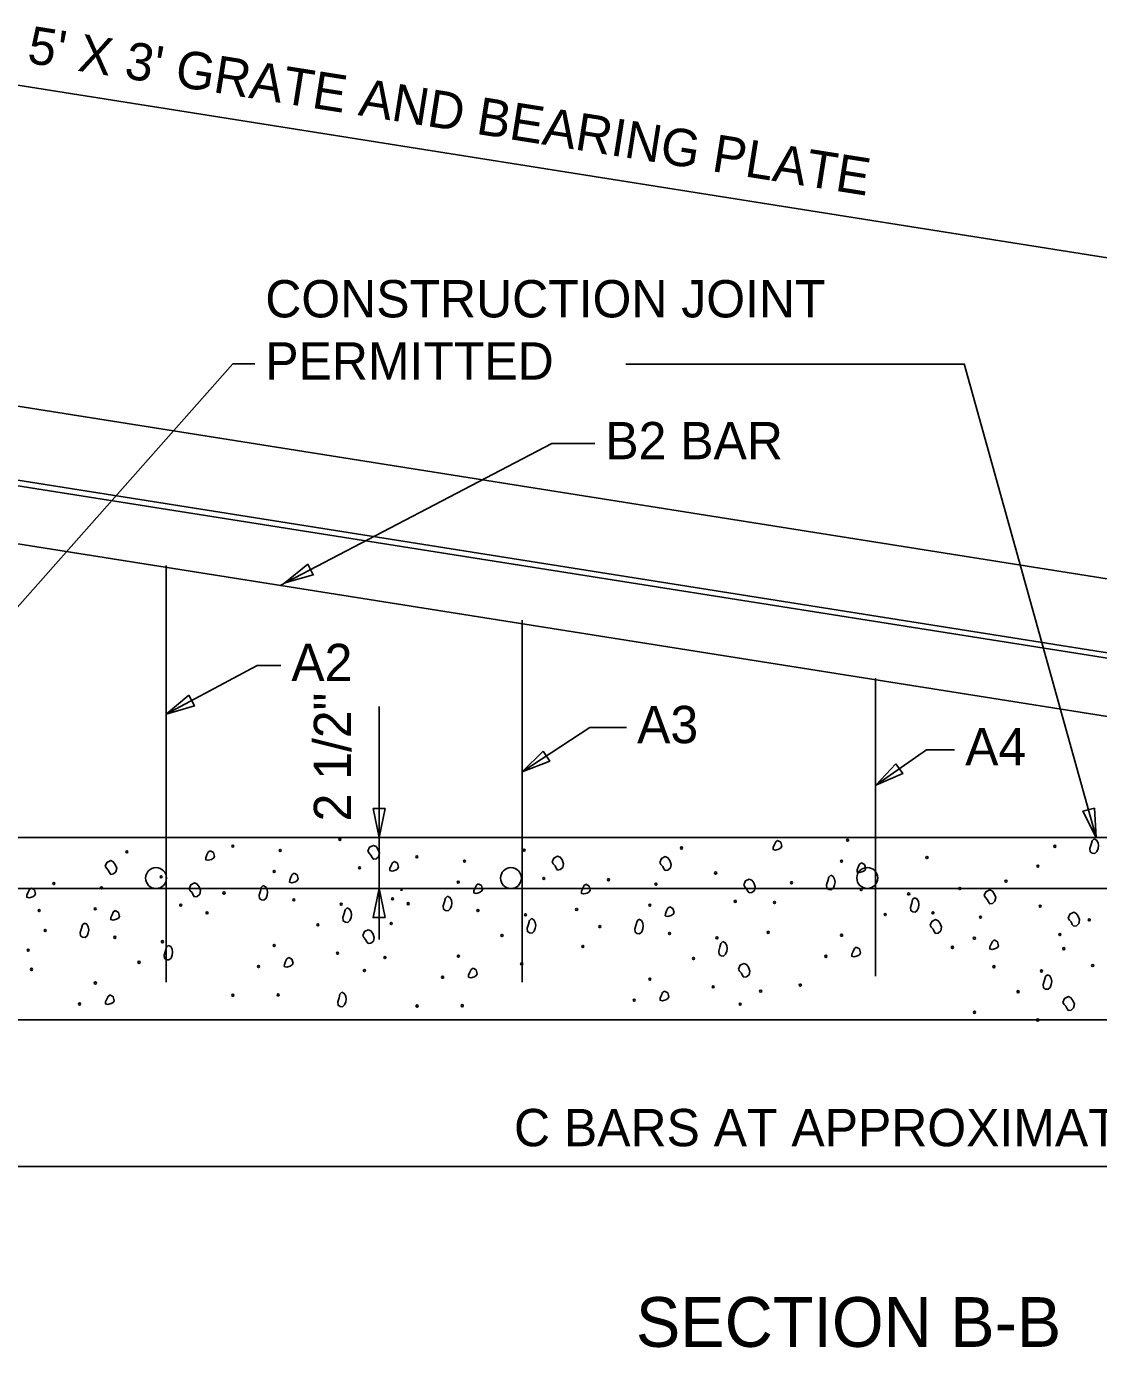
# Model space of a CAD drawing. Extents: x -439.2 to -407.9, y -458.1 to -436.2.
# Drawn here: x -435.83 to -431.52, y -451.85 to -446.54 of the extents above; entities that cross this region are included whole.
import ezdxf

# ---------------------------------------------------------------- set-up
doc = ezdxf.new("R2010")
doc.units = 0
doc.layers.add('Level 4', color=7, linetype='Continuous')
doc.layers.add('Level 45', color=7, linetype='Continuous')

msp = doc.modelspace()

# ---------------------------------------------------------------- linework, layer by layer
at = {"layer": 'Level 4'}
for p, q in [((-436.1395, -446.7284), (-430.9827, -447.5452)), ((-439.1627, -447.54), (-425.6904, -449.6734)), ((-436.6846, -449.7952), (-434.9984, -447.8922)), ((-434.9984, -447.8922), (-434.9111, -447.8922)), ((-433.4201, -447.8926), (-432.0607, -447.8926)), ((-431.5296, -449.7955), (-432.0609, -447.8922)), ((-434.8086, -448.7823), (-433.7176, -448.2124)), ((-433.7176, -448.2124), (-433.5449, -448.2124)), ((-436.4245, -448.2926), (-431.261, -449.11)), ((-436.4193, -448.2716), (-431.2564, -449.0896)), ((-436.5705, -448.5037), (-430.4973, -449.4655)), ((-435.2674, -448.7021), (-435.2674, -450.3769)), ((-433.8363, -448.9226), (-433.8363, -450.3769)), ((-435.2674, -449.3001), (-434.9012, -449.104)), ((-434.9012, -449.104), (-434.8066, -449.104)), ((-432.4167, -449.1557), (-432.4167, -450.3527)), ((-434.4116, -450.2055), (-434.4116, -449.2691)), ((-433.8363, -449.5318), (-433.5653, -449.3534)), ((-433.5653, -449.3534), (-433.4172, -449.3534)), ((-432.4162, -449.585), (-432.2115, -449.4425)), ((-432.2115, -449.4425), (-432.0991, -449.4425)), ((-436.4193, -449.7952), (-425.6904, -449.7952)), ((-436.9348, -450.001), (-431.0317, -450.001)), ((-434.3258, -450.0072), (-434.3171, -450.0072)), ((-437.1984, -450.5281), (-425.6904, -450.5281)), ((-425.6902, -451.1174), (-437.1989, -451.1174))]:
    msp.add_line(p, q, dxfattribs=at)
for points in [[(-434.6982, -448.6974), (-434.79, -448.7725), (-434.6759, -448.7401)], [(-435.1764, -449.224), (-435.2674, -449.3001), (-435.1536, -449.2665)], [(-433.7525, -449.4478), (-433.8363, -449.5318), (-433.726, -449.4881)], [(-432.3347, -449.4988), (-432.4162, -449.585), (-432.3071, -449.5384)], [(-434.4357, -449.679), (-434.4116, -449.7952), (-434.3875, -449.679)], [(-431.5376, -449.6771), (-431.5296, -449.7955), (-431.584, -449.69)], [(-434.456, -449.8506), (-434.4495, -449.8349), (-434.434, -449.8272), (-434.4237, -449.8321), (-434.4158, -449.8428), (-434.4101, -449.8581), (-434.4132, -449.8727), (-434.4232, -449.8815), (-434.434, -449.8831), (-434.4394, -449.876), (-434.4443, -449.8662), (-434.4514, -449.8586), (-434.456, -449.8506)], [(-432.8101, -449.8072), (-432.8179, -449.813), (-432.8231, -449.824), (-432.8278, -449.8353), (-432.8283, -449.8435), (-432.8188, -449.8458), (-432.8049, -449.8422), (-432.7971, -449.8374), (-432.7932, -449.8305), (-432.7975, -449.8146), (-432.8101, -449.8072)], [(-431.5384, -449.801), (-431.5463, -449.8084), (-431.5501, -449.823), (-431.5554, -449.8398), (-431.554, -449.8529), (-431.5458, -449.8585), (-431.5358, -449.8594), (-431.5274, -449.852), (-431.5228, -449.8399), (-431.521, -449.8282), (-431.5228, -449.8165), (-431.5288, -449.8057), (-431.5384, -449.801)], [(-435.5116, -449.9112), (-435.505, -449.8955), (-435.4896, -449.8878), (-435.4793, -449.8927), (-435.4714, -449.9034), (-435.4657, -449.9187), (-435.4688, -449.9333), (-435.4788, -449.9421), (-435.4896, -449.9436), (-435.495, -449.9366), (-435.4999, -449.9268), (-435.5069, -449.9192), (-435.5116, -449.9112)], [(-435.0899, -449.8484), (-435.0977, -449.8542), (-435.1029, -449.8652), (-435.1076, -449.8765), (-435.1081, -449.8847), (-435.0986, -449.887), (-435.0847, -449.8834), (-435.0769, -449.8786), (-435.073, -449.8717), (-435.0773, -449.8558), (-435.0899, -449.8484)], [(-434.3498, -449.8914), (-434.3576, -449.8973), (-434.3628, -449.9083), (-434.3676, -449.9195), (-434.368, -449.9277), (-434.3585, -449.9301), (-434.3446, -449.9264), (-434.3369, -449.9217), (-434.3329, -449.9148), (-434.3372, -449.8988), (-434.3498, -449.8914)], [(-433.716, -449.8936), (-433.7094, -449.8779), (-433.6939, -449.8703), (-433.6836, -449.8751), (-433.6757, -449.8858), (-433.67, -449.9011), (-433.6731, -449.9157), (-433.6832, -449.9245), (-433.6939, -449.9261), (-433.6993, -449.919), (-433.7043, -449.9092), (-433.7113, -449.9016), (-433.716, -449.8936)], [(-433.2835, -449.8958), (-433.2769, -449.8801), (-433.2614, -449.8724), (-433.2511, -449.8773), (-433.2432, -449.888), (-433.2375, -449.9033), (-433.2406, -449.9179), (-433.2507, -449.9267), (-433.2614, -449.9283), (-433.2668, -449.9212), (-433.2718, -449.9114), (-433.2788, -449.9038), (-433.2835, -449.8958)], [(-434.7528, -449.9384), (-434.7606, -449.9443), (-434.7658, -449.9552), (-434.7706, -449.9665), (-434.771, -449.9747), (-434.7615, -449.977), (-434.7477, -449.9734), (-434.7399, -449.9687), (-434.736, -449.9617), (-434.7402, -449.9458), (-434.7528, -449.9384)], [(-432.5969, -449.9473), (-432.6048, -449.9547), (-432.6086, -449.9693), (-432.6139, -449.9861), (-432.6125, -449.9992), (-432.6043, -450.0048), (-432.5943, -450.0057), (-432.5858, -449.9983), (-432.5813, -449.9862), (-432.5795, -449.9745), (-432.5813, -449.9628), (-432.5873, -449.952), (-432.5969, -449.9473)], [(-432.473, -449.8972), (-432.4808, -449.9031), (-432.486, -449.914), (-432.4908, -449.9253), (-432.4912, -449.9335), (-432.4817, -449.9358), (-432.4679, -449.9322), (-432.4601, -449.9274), (-432.4562, -449.9205), (-432.4604, -449.9046), (-432.473, -449.8972)], [(-435.8084, -449.999), (-435.8162, -450.0048), (-435.8214, -450.0158), (-435.8262, -450.0271), (-435.8266, -450.0353), (-435.8171, -450.0376), (-435.8032, -450.034), (-435.7955, -450.0292), (-435.7916, -450.0223), (-435.7958, -450.0064), (-435.8084, -449.999)], [(-435.1746, -450.0012), (-435.168, -449.9855), (-435.1525, -449.9778), (-435.1422, -449.9827), (-435.1343, -449.9934), (-435.1286, -450.0087), (-435.1317, -450.0233), (-435.1418, -450.0321), (-435.1525, -450.0337), (-435.158, -450.0266), (-435.1629, -450.0168), (-435.1699, -450.0092), (-435.1746, -450.0012)], [(-434.8767, -449.9885), (-434.8846, -449.9959), (-434.8884, -450.0105), (-434.8937, -450.0273), (-434.8922, -450.0404), (-434.8841, -450.046), (-434.8741, -450.0469), (-434.8656, -450.0395), (-434.8611, -450.0274), (-434.8593, -450.0157), (-434.8611, -450.004), (-434.8671, -449.9932), (-434.8767, -449.9885)], [(-434.3875, -450.1171), (-434.4116, -450.001), (-434.4357, -450.1171)], [(-434.0128, -449.9814), (-434.0206, -449.9873), (-434.0258, -449.9983), (-434.0305, -450.0095), (-434.031, -450.0177), (-434.0215, -450.0201), (-434.0076, -450.0164), (-433.9998, -450.0117), (-433.9959, -450.0048), (-434.0002, -449.9888), (-434.0128, -449.9814)], [(-433.5803, -449.9836), (-433.5881, -449.9895), (-433.5933, -450.0004), (-433.598, -450.0117), (-433.5984, -450.0199), (-433.589, -450.0222), (-433.5751, -450.0186), (-433.5673, -450.0138), (-433.5634, -450.0069), (-433.5676, -449.991), (-433.5803, -449.9836)], [(-432.9464, -449.9858), (-432.9398, -449.9701), (-432.9243, -449.9624), (-432.9141, -449.9673), (-432.9062, -449.978), (-432.9005, -449.9933), (-432.9036, -450.0079), (-432.9136, -450.0167), (-432.9243, -450.0183), (-432.9298, -450.0112), (-432.9347, -450.0014), (-432.9417, -449.9938), (-432.9464, -449.9858)], [(-434.1366, -450.0315), (-434.1445, -450.0389), (-434.1483, -450.0536), (-434.1536, -450.0703), (-434.1522, -450.0834), (-434.144, -450.089), (-434.134, -450.0899), (-434.1256, -450.0825), (-434.121, -450.0704), (-434.1192, -450.0587), (-434.121, -450.0471), (-434.127, -450.0363), (-434.1366, -450.0315)], [(-432.2598, -450.0373), (-432.2678, -450.0447), (-432.2715, -450.0593), (-432.2768, -450.0761), (-432.2754, -450.0892), (-432.2672, -450.0948), (-432.2572, -450.0957), (-432.2488, -450.0883), (-432.2443, -450.0762), (-432.2424, -450.0645), (-432.2443, -450.0528), (-432.2503, -450.042), (-432.2598, -450.0373)], [(-431.9797, -450.0292), (-431.9732, -450.0135), (-431.9577, -450.0058), (-431.9474, -450.0107), (-431.9395, -450.0214), (-431.9338, -450.0367), (-431.9369, -450.0513), (-431.9469, -450.0601), (-431.9577, -450.0616), (-431.9631, -450.0546), (-431.9681, -450.0448), (-431.9751, -450.0372), (-431.9797, -450.0292)], [(-435.4714, -450.089), (-435.4792, -450.0949), (-435.4844, -450.1058), (-435.4891, -450.1171), (-435.4896, -450.1253), (-435.4801, -450.1276), (-435.4662, -450.124), (-435.4584, -450.1192), (-435.4545, -450.1123), (-435.4588, -450.0964), (-435.4714, -450.089)], [(-434.5396, -450.0785), (-434.5476, -450.0859), (-434.5513, -450.1005), (-434.5566, -450.1173), (-434.5552, -450.1304), (-434.547, -450.136), (-434.537, -450.1369), (-434.5286, -450.1295), (-434.5241, -450.1174), (-434.5222, -450.1057), (-434.5241, -450.0941), (-434.5301, -450.0832), (-434.5396, -450.0785)], [(-433.2432, -450.0736), (-433.251, -450.0795), (-433.2562, -450.0904), (-433.261, -450.1017), (-433.2614, -450.1099), (-433.2519, -450.1123), (-433.238, -450.1086), (-433.2303, -450.1039), (-433.2264, -450.0969), (-433.2306, -450.081), (-433.2432, -450.0736)], [(-431.6427, -450.1192), (-431.6361, -450.1035), (-431.6206, -450.0958), (-431.6103, -450.1007), (-431.6024, -450.1114), (-431.5968, -450.1267), (-431.5999, -450.1413), (-431.6099, -450.1501), (-431.6206, -450.1517), (-431.6261, -450.1446), (-431.631, -450.1348), (-431.638, -450.1272), (-431.6427, -450.1192)], [(-435.5952, -450.1391), (-435.6032, -450.1465), (-435.6069, -450.1611), (-435.6122, -450.1779), (-435.6108, -450.191), (-435.6026, -450.1966), (-435.5926, -450.1975), (-435.5842, -450.1901), (-435.5796, -450.178), (-435.5778, -450.1663), (-435.5796, -450.1546), (-435.5857, -450.1438), (-435.5952, -450.1391)], [(-433.7996, -450.1215), (-433.8075, -450.1289), (-433.8112, -450.1436), (-433.8165, -450.1603), (-433.8151, -450.1734), (-433.807, -450.179), (-433.797, -450.1799), (-433.7885, -450.1725), (-433.784, -450.1604), (-433.7822, -450.1487), (-433.784, -450.1371), (-433.79, -450.1263), (-433.7996, -450.1215)], [(-433.3671, -450.1237), (-433.375, -450.1311), (-433.3787, -450.1457), (-433.384, -450.1625), (-433.3826, -450.1756), (-433.3744, -450.1812), (-433.3645, -450.1821), (-433.356, -450.1747), (-433.3515, -450.1626), (-433.3497, -450.1509), (-433.3515, -450.1393), (-433.3575, -450.1284), (-433.3671, -450.1237)], [(-432.1973, -450.1484), (-432.1907, -450.1326), (-432.1752, -450.125), (-432.1649, -450.1298), (-432.1571, -450.1406), (-432.1514, -450.1558), (-432.1545, -450.1704), (-432.1645, -450.1793), (-432.1752, -450.1808), (-432.1807, -450.1738), (-432.1856, -450.1639), (-432.1926, -450.1564), (-432.1973, -450.1484)], [(-434.4771, -450.1896), (-434.4705, -450.1738), (-434.455, -450.1662), (-434.4447, -450.1711), (-434.4369, -450.1818), (-434.4311, -450.197), (-434.4343, -450.2116), (-434.4443, -450.2205), (-434.455, -450.222), (-434.4605, -450.215), (-434.4654, -450.2051), (-434.4724, -450.1976), (-434.4771, -450.1896)], [(-433.03, -450.2137), (-433.038, -450.2211), (-433.0417, -450.2357), (-433.047, -450.2525), (-433.0456, -450.2656), (-433.0374, -450.2712), (-433.0274, -450.2721), (-433.019, -450.2647), (-433.0144, -450.2526), (-433.0126, -450.2409), (-433.0144, -450.2293), (-433.0205, -450.2184), (-433.03, -450.2137)], [(-431.9395, -450.207), (-431.9473, -450.2129), (-431.9525, -450.2238), (-431.9572, -450.2351), (-431.9577, -450.2433), (-431.9482, -450.2456), (-431.9343, -450.242), (-431.9265, -450.2372), (-431.9226, -450.2303), (-431.9269, -450.2144), (-431.9395, -450.207)], [(-435.2582, -450.2291), (-435.2661, -450.2365), (-435.2699, -450.2511), (-435.2752, -450.2679), (-435.2738, -450.281), (-435.2656, -450.2866), (-435.2556, -450.2875), (-435.2472, -450.2801), (-435.2426, -450.268), (-435.2408, -450.2563), (-435.2426, -450.2446), (-435.2486, -450.2338), (-435.2582, -450.2291)], [(-432.4941, -450.2361), (-432.5019, -450.242), (-432.5071, -450.253), (-432.5118, -450.2642), (-432.5123, -450.2725), (-432.5028, -450.2748), (-432.4889, -450.2712), (-432.4811, -450.2664), (-432.4772, -450.2595), (-432.4815, -450.2435), (-432.4941, -450.2361)], [(-434.7739, -450.2773), (-434.7817, -450.2832), (-434.7869, -450.2942), (-434.7916, -450.3054), (-434.7921, -450.3137), (-434.7826, -450.316), (-434.7687, -450.3124), (-434.7609, -450.3076), (-434.757, -450.3007), (-434.7613, -450.2847), (-434.7739, -450.2773)], [(-434.0338, -450.3203), (-434.0416, -450.3262), (-434.0468, -450.3372), (-434.0516, -450.3485), (-434.052, -450.3567), (-434.0425, -450.359), (-434.0286, -450.3554), (-434.0209, -450.3506), (-434.017, -450.3437), (-434.0212, -450.3278), (-434.0338, -450.3203)], [(-432.9675, -450.3248), (-432.9609, -450.309), (-432.9454, -450.3014), (-432.9351, -450.3063), (-432.9272, -450.317), (-432.9215, -450.3322), (-432.9246, -450.3468), (-432.9347, -450.3557), (-432.9454, -450.3572), (-432.9509, -450.3502), (-432.9558, -450.3403), (-432.9628, -450.3328), (-432.9675, -450.3248)], [(-431.7263, -450.3471), (-431.7342, -450.3545), (-431.738, -450.3691), (-431.7433, -450.3859), (-431.7419, -450.399), (-431.7337, -450.4046), (-431.7237, -450.4055), (-431.7153, -450.3981), (-431.7107, -450.386), (-431.7089, -450.3743), (-431.7107, -450.3626), (-431.7167, -450.3518), (-431.7263, -450.3471)], [(-434.5607, -450.4174), (-434.5686, -450.4249), (-434.5724, -450.4395), (-434.5777, -450.4563), (-434.5763, -450.4694), (-434.5681, -450.475), (-434.5581, -450.4758), (-434.5497, -450.4685), (-434.5451, -450.4564), (-434.5433, -450.4446), (-434.5451, -450.433), (-434.5511, -450.4222), (-434.5607, -450.4174)], [(-433.2643, -450.4125), (-433.2721, -450.4184), (-433.2773, -450.4294), (-433.282, -450.4406), (-433.2825, -450.4489), (-433.273, -450.4512), (-433.2591, -450.4476), (-433.2513, -450.4428), (-433.2474, -450.4359), (-433.2517, -450.42), (-433.2643, -450.4125)], [(-435.4925, -450.4279), (-435.5003, -450.4338), (-435.5054, -450.4448), (-435.5102, -450.456), (-435.5106, -450.4643), (-435.5012, -450.4666), (-435.4873, -450.463), (-435.4795, -450.4582), (-435.4756, -450.4513), (-435.4798, -450.4353), (-435.4925, -450.4279)], [(-431.6638, -450.4582), (-431.6572, -450.4424), (-431.6417, -450.4348), (-431.6314, -450.4396), (-431.6235, -450.4504), (-431.6178, -450.4656), (-431.6209, -450.4802), (-431.631, -450.4891), (-431.6417, -450.4906), (-431.6471, -450.4835), (-431.6521, -450.4737), (-431.6591, -450.4662), (-431.6638, -450.4582)]]:
    msp.add_lwpolyline(points, close=True, dxfattribs=at)
for centre in [(-435.3075, -449.9585), (-433.8814, -449.9585), (-432.4499, -449.9581)]:
    msp.add_circle(centre, 0.042, dxfattribs=at)
for centre, start, end in [((-434.9994, -449.8299), 0, 180), ((-434.9994, -449.8299), 180, 0), ((-434.5688, -449.8029), 0, 180), ((-434.5688, -449.8029), 180, 0), ((-433.8287, -449.846), 0, 180), ((-433.1963, -449.8377), 0, 180), ((-433.1963, -449.8377), 180, 0), ((-432.5289, -449.8062), 0, 180), ((-432.5289, -449.8062), 180, 0), ((-431.6961, -449.8309), 0, 180), ((-431.6961, -449.8309), 180, 0), ((-435.4245, -449.8531), 0, 180), ((-435.4245, -449.8531), 180, 0), ((-434.8087, -449.8474), 0, 180), ((-434.8087, -449.8474), 180, 0), ((-434.2594, -449.8729), 0, 180), ((-434.2594, -449.8729), 180, 0), ((-434.0686, -449.8904), 0, 180), ((-434.0686, -449.8904), 180, 0), ((-433.8287, -449.846), 180, 0), ((-432.5534, -449.8907), 0, 180), ((-432.5534, -449.8907), 180, 0), ((-432.21, -449.8758), 0, 180), ((-432.21, -449.8758), 180, 0), ((-434.8332, -449.9319), 0, 180), ((-434.8332, -449.9319), 180, 0), ((-434.4898, -449.917), 0, 180), ((-434.4898, -449.917), 180, 0), ((-433.0592, -449.9381), 0, 180), ((-433.0592, -449.9381), 180, 0), ((-431.7643, -449.9105), 0, 180), ((-431.7643, -449.9105), 180, 0), ((-435.718, -449.9805), 0, 180), ((-435.718, -449.9805), 180, 0), ((-435.5272, -449.998), 0, 180), ((-435.5272, -449.998), 180, 0), ((-435.2873, -449.9535), 0, 180), ((-435.2873, -449.9535), 180, 0), ((-434.0932, -449.975), 0, 180), ((-434.0932, -449.975), 180, 0), ((-433.7498, -449.96), 0, 180), ((-433.7498, -449.96), 180, 0), ((-433.4898, -449.9651), 0, 180), ((-433.4898, -449.9651), 180, 0), ((-433.299, -449.9826), 0, 180), ((-433.299, -449.9826), 180, 0), ((-432.7546, -449.9772), 0, 180), ((-432.7546, -449.9772), 180, 0), ((-432.4745, -450.0048), 0, 180), ((-432.0777, -450.0004), 0, 180), ((-432.0777, -450.0004), 180, 0), ((-431.8926, -449.9711), 0, 180), ((-431.8926, -449.9711), 180, 0), ((-435.0344, -450.0184), 0, 180), ((-435.0344, -450.0184), 180, 0), ((-434.7543, -450.046), 0, 180), ((-434.7543, -450.046), 180, 0), ((-434.3575, -450.0416), 0, 180), ((-434.3575, -450.0416), 180, 0), ((-432.9802, -450.0522), 0, 180), ((-432.9802, -450.0522), 180, 0), ((-432.8228, -450.0568), 0, 180), ((-432.4745, -450.0048), 180, 0), ((-432.2837, -450.0223), 0, 180), ((-432.2837, -450.0223), 180, 0), ((-435.7774, -450.0889), 0, 180), ((-435.7774, -450.0889), 180, 0), ((-435.5518, -450.0825), 0, 180), ((-435.5518, -450.0825), 180, 0), ((-435.2084, -450.0676), 0, 180), ((-435.2084, -450.0676), 180, 0), ((-435.1026, -450.098), 0, 180), ((-435.1026, -450.098), 180, 0), ((-434.5635, -450.0635), 0, 180), ((-434.5635, -450.0635), 180, 0), ((-434.2943, -450.0614), 0, 180), ((-434.2943, -450.0614), 180, 0), ((-434.0142, -450.089), 0, 180), ((-434.0142, -450.089), 180, 0), ((-433.8235, -450.1065), 0, 180), ((-433.8235, -450.1065), 180, 0), ((-433.6175, -450.0846), 0, 180), ((-433.6175, -450.0846), 180, 0), ((-433.3236, -450.0672), 0, 180), ((-433.3236, -450.0672), 180, 0), ((-432.8228, -450.0568), 180, 0), ((-432.3777, -450.1052), 0, 180), ((-432.3777, -450.1052), 180, 0), ((-432.1861, -450.0985), 0, 180), ((-432.1861, -450.0985), 180, 0), ((-431.7555, -450.0715), 0, 180), ((-431.7555, -450.0715), 180, 0), ((-434.6575, -450.1464), 0, 180), ((-434.6575, -450.1464), 180, 0), ((-434.3625, -450.1411), 0, 180), ((-434.3625, -450.1411), 180, 0), ((-433.5248, -450.1536), 0, 180), ((-433.5248, -450.1536), 180, 0), ((-431.9953, -450.116), 0, 180), ((-431.9953, -450.116), 180, 0), ((-431.5579, -450.1266), 0, 180), ((-431.5579, -450.1266), 180, 0), ((-435.753, -450.169), 0, 180), ((-435.753, -450.169), 180, 0), ((-435.4729, -450.1966), 0, 180), ((-435.4729, -450.1966), 180, 0), ((-435.2821, -450.2141), 0, 180), ((-435.2821, -450.2141), 180, 0), ((-433.9174, -450.1894), 0, 180), ((-433.9174, -450.1894), 180, 0), ((-433.2447, -450.1812), 0, 180), ((-433.2447, -450.1812), 180, 0), ((-433.0539, -450.1987), 0, 180), ((-433.0539, -450.1987), 180, 0), ((-432.8479, -450.1768), 0, 180), ((-432.8479, -450.1768), 180, 0), ((-432.553, -450.1884), 0, 180), ((-432.553, -450.1884), 180, 0), ((-432.0199, -450.2005), 0, 180), ((-432.0199, -450.2005), 180, 0), ((-431.6765, -450.1856), 0, 180), ((-431.6765, -450.1856), 180, 0), ((-435.8211, -450.2486), 0, 180), ((-435.8211, -450.2486), 180, 0), ((-434.8328, -450.2296), 0, 180), ((-434.8328, -450.2296), 180, 0), ((-434.5785, -450.2604), 0, 180), ((-434.5785, -450.2604), 180, 0), ((-433.5929, -450.2332), 0, 180), ((-433.5929, -450.2332), 180, 0), ((-432.108, -450.2368), 0, 180), ((-432.108, -450.2368), 180, 0), ((-431.6607, -450.2421), 0, 180), ((-431.6607, -450.2421), 180, 0), ((-435.376, -450.297), 0, 180), ((-435.376, -450.297), 180, 0), ((-434.8961, -450.3141), 0, 180), ((-434.8961, -450.3141), 180, 0), ((-434.3878, -450.278), 0, 180), ((-434.3878, -450.278), 180, 0), ((-434.0928, -450.2726), 0, 180), ((-434.0928, -450.2726), 180, 0), ((-433.8385, -450.3035), 0, 180), ((-433.8385, -450.3035), 180, 0), ((-433.1479, -450.2816), 0, 180), ((-433.1479, -450.2816), 180, 0), ((-432.6163, -450.2729), 0, 180), ((-432.6163, -450.2729), 180, 0), ((-431.941, -450.3146), 0, 180), ((-431.941, -450.3146), 180, 0), ((-431.5442, -450.3102), 0, 180), ((-431.5442, -450.3102), 180, 0), ((-435.8077, -450.3253), 0, 180), ((-435.8077, -450.3253), 180, 0), ((-434.4704, -450.3303), 0, 180), ((-434.4704, -450.3303), 180, 0), ((-434.1561, -450.3572), 0, 180), ((-434.1561, -450.3572), 180, 0), ((-433.3232, -450.3648), 0, 180), ((-433.3232, -450.3648), 180, 0), ((-431.7502, -450.3321), 0, 180), ((-431.7502, -450.3321), 180, 0), ((-435.5514, -450.3802), 0, 180), ((-435.5514, -450.3802), 180, 0), ((-434.9989, -450.4296), 0, 180), ((-434.8172, -450.4282), 0, 180), ((-433.0689, -450.3956), 0, 180), ((-433.0689, -450.3956), 180, 0), ((-432.8782, -450.4132), 0, 180), ((-432.8782, -450.4132), 180, 0), ((-432.7191, -450.3884), 0, 180), ((-432.7191, -450.3884), 180, 0), ((-431.8441, -450.415), 0, 180), ((-431.8441, -450.415), 180, 0), ((-435.6147, -450.4647), 0, 180), ((-435.6147, -450.4647), 180, 0), ((-434.9989, -450.4296), 180, 0), ((-434.8172, -450.4282), 180, 0), ((-434.2589, -450.4726), 0, 180), ((-434.2589, -450.4726), 180, 0), ((-434.0771, -450.4712), 0, 180), ((-434.0771, -450.4712), 180, 0), ((-433.3865, -450.4493), 0, 180), ((-433.3865, -450.4493), 180, 0), ((-432.9608, -450.4655), 0, 180), ((-432.9608, -450.4655), 180, 0), ((-432.0195, -450.4982), 0, 180), ((-432.0195, -450.4982), 180, 0), ((-431.7652, -450.529), 0, 180), ((-431.7652, -450.529), 180, 0)]:
    msp.add_arc(centre, 0.00416, start, end, dxfattribs=at)

# ---------------------------------------------------------------- texts
for s, height, p in [('CONSTRUCTION JOINT', 0.15, (-434.8686, -447.7052)), ('PERMITTED', 0.15, (-434.8686, -447.9552)), ('B2 BAR', 0.15, (-433.5024, -448.2754)), ('A2', 0.15, (-434.764, -449.167)), ('A3', 0.15, (-433.3747, -449.4164)), ('A4', 0.15, (-432.0565, -449.5055)), ('SECTION B-B', 0.2, (-433.3796, -451.8426))]:
    msp.add_text(s, height=height, dxfattribs=at).set_placement(p)
at = {"layer": 'Level 45'}
for s, rotation, p in [("5' X 3' GRATE AND BEARING PLATE", 351, (-435.8297, -446.6812)), ('2 1/2"', 90, (-434.5237, -449.7307))]:
    msp.add_text(s, height=0.15, rotation=rotation, dxfattribs=at).set_placement(p)
msp.add_text('C BARS AT APPROXIMATELY 12" CTRS.', height=0.15, dxfattribs=at).set_placement((-433.8694, -451.0363))

doc.saveas('drawing.dxf')
